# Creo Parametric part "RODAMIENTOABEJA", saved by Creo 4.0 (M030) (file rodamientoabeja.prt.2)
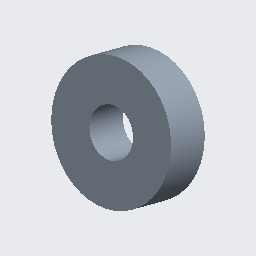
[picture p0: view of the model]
Units: millimeter Newton Second (mmNs); MM, TONNE, SECS

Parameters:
  MODELED_BY = "aj"

Created from: MMNS_PART_SOLID.PRT

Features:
  1. datum plane "RIGHT"
  2. datum plane "TOP"
  3. datum plane "FRONT"
  4. coordinate system
  5. extrusion "Extrude 1"
  6. datum axis "A_3"

Surfaces: 2 plane, 2 cylinder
